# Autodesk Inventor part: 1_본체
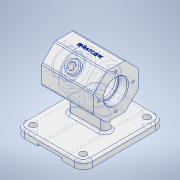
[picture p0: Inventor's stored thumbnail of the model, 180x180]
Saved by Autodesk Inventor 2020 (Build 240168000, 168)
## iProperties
Created: 2022-10
Part Number: 1_본체
Material: 알루미늄 6061
Document SubType Name: Modeling
Designer: USER
Density: 2.7 g/cm^3
Appearance: 알루미늄 - 평지
Mass: 559.154 g
Surface Area: 567.652 cm^2
Volume: 207.094 cm^3
Author: USER
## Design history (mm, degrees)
sketch "스케치1"
  geometry: L1 (46, 55)-(-46, 55); L2 (-46, 55)-(-46, -55); L3 (-46, -55)-(46, -55); L4 (46, -55)-(46, 55); L5 (46, 55)-(-46, -55); L6 (-46, 55)-(46, -55); 1 further point
  constraints: 12 end point, 2 midpoint, 2 parallel, 1 horizontal, 1 perpendicular
  dimensions: "d0" = 92 distance of L2.end L3.end; "d1" = 110 distance of L3.end L1.start
extrude "돌출1" new body sketch "스케치1" distance "d2" = 10; taper "d3" = 0 deg
sketch "스케치2"
  geometry: L1 (30, 3)-(62, 3); L2 (62, 3)-(62, 0); L3 (62, 0)-(30, 0); L4 (30, 0)-(30, 3); L5 (0, 0)-(92, 0) reference; 2 further points
  constraints: 8 end point, 2 midpoint, 2 parallel, 1 horizontal, 1 perpendicular
  dimensions: "d4" = 32 distance of L2.end L3.end; "d5" = 3 distance of L1.end L2.end
extrude "돌출2" cut sketch "스케치2" extent not by distance; stored distance "d6" = 0; taper "d7" = 0 deg
fillet "모깎기1" dims "d8" = 12
sketch "스케치3"
  geometry: L1 (74.426, 30)-(92, 12.426); L2 (92, 12.426)-(92, -12.426); L3 (92, -12.426)-(74.426, -30); L4 (74.426, -30)-(49.574, -30); L5 (49.574, -30)-(32, -12.426); L6 (32, -12.426)-(32, 12.426); L7 (32, 12.426)-(49.574, 30); L8 (49.574, 30)-(74.426, 30); L9 (0, -55)-(0, -43) reference; L10 (0, 0)-(62, 0); C1 r 30 at (62, 0); 1 further point
  constraints: 18 end point, 2 coincident, 2 horizontal, 1 centre point, 1 tangent, 17 other
  dimensions: "d9" = 62 distance from line of L9 point (62, 0); "d10" = 60 diameter of C1
extrude "돌출3" join sketch "스케치3" stored distance "d11" = 70; taper "d12" = 0 deg
sketch "스케치4"
  geometry: L1 (-20, 0)-(20, 0); L2 (-20, -6)-(20, -6); L3 (20, 6)-(-20, 6); A1 r 6 centre (-20, 0) between (-20, 6) and (-20, -6); A2 r 6 centre (20, 0) between (20, -6) and (20, 6); 2 further points
  constraints: 8 end point, 4 point on circle, 4 tangent, 2 centre point, 1 coincident, 1 horizontal, 1 midpoint, 1 parallel
  dimensions: "d13" = 40 distance of L1.start L1.end; "d14" = 12 distance between parallel lines of L3 L2
extrude "돌출4" join sketch "스케치4" stored distance "d15" = 70; taper "d16" = 0 deg
sketch "스케치5"
  geometry: L1 (74.426, 30)-(92, 12.426) reference; L2 (83.213, 21.213)-(88.87, 15.556); L3 (88.87, 15.556)-(92.406, 19.092); L4 (92.406, 19.092)-(86.749, 24.749); L5 (86.749, 24.749)-(83.213, 21.213); 1 further point
  constraints: 8 end point, 2 parallel, 1 midpoint, 1 perpendicular, 1 point on line
  dimensions: "d17" = 16 diameter of L3 L5; "d18" = 5 distance between parallel lines of L1 L4
revolve "회전1" sketch "스케치5" stored, may be unused: angle "d19" = 90 deg
sketch "스케치6"
  geometry: L1 (-35, 74.426)-(-35, 49.574) reference; L2 (-35, 92)-(35, 92) reference; L3 (-35, 62)-(0, 62); L4 (0, 92)-(0, 62); L5 (-20, 62)-(20, 62); L6 (20, 62)-(20, 84); L7 (17, 87)-(-17, 87); L8 (-20, 84)-(-20, 62); A1 r 3 centre (-17, 84) between (-17, 87) and (-20, 84); A2 r 3 centre (17, 84) between (20, 84) and (17, 87); 3 further points
  constraints: 12 end point, 4 point on circle, 4 point on line, 4 tangent, 3 midpoint, 2 centre point, 2 horizontal, 2 parallel, 1 equal radius, 1 perpendicular, 1 vertical
  dimensions: "d20" = 50 diameter of L7 L5; "d21" = 40 distance of point (20, 87) point (-20, 87); "d22" = 3 radius of A1
revolve "회전2" sketch "스케치6" stored, may be unused: angle "d23" = 90 deg
sketch "스케치7"
  geometry: L1 (-35, 74.426)-(-35, 49.574) reference; L2 (-35, 62)-(-20, 62); L3 (-20, 84)-(-20, 40) reference; L4 (-35, 62)-(-35, 78); L5 (-35, 78)-(-23, 78); L6 (-23, 78)-(-23, 76); L7 (-23, 76)-(-20, 76); L8 (-20, 76)-(-20, 62); 1 further point
  constraints: 12 end point, 3 perpendicular, 2 midpoint, 2 vertical, 1 point on line
  dimensions: "d24" = 32 diameter of L5 L2; "d25" = 28 diameter of L7 L2; "d26" = 12 distance between parallel lines of L4 L6
revolve "회전3" sketch "스케치7" stored, may be unused: angle "d27" = 90 deg
chamfer "모따기1" distance "d28" = 1; stored, may be unused: second distance "d29" = 2, angle "d30" = 45 deg
fillet "모깎기2" dims "d31" = 0.3
sketch "스케치8" dims "d32" = 46
  geometry: L1 (0, 62)-(0, 85); C1 r 17 at (0, 62) reference; 2 further points
  constraints: 2 coincident, 2 end point, 1 vertical, 1 vertical alignment, 2 other
hole "구멍1" sketch "스케치8" at (0, 85) diameter "d33" = 3.242; stored, may be unused: countersink angle "d37" = 90 deg, drill point angle "d39" = 118 deg; dims "d34" = 8, "d35" = 4, "d36" = 2, "d38" = 10
sketch "스케치9"
  geometry: C1 r 8 at (0, 0) reference; C2 r 4 at (0, 0); 1 further point
  constraints: 1 centre point, 1 coincident
  dimensions: "d43" = 8 diameter of C2
extrude "돌출5" cut sketch "스케치9" stored distance "d44" = 70; taper "d45" = 0 deg
sketch "스케치10"
  geometry: L1 (20, -6)-(-20, -6) reference; L2 (-20, 6)-(20, 6) reference; L3 (34, 55)-(-34, 55) reference; L4 (-46, 43)-(-46, -43) reference; L5 (-34, -55)-(34, -55) reference; L6 (46, -43)-(46, 43) reference; A1 r 6 centre (-20, 0) between (-20, 6) and (-20, -6) reference; A2 r 6 centre (20, 0) between (20, -6) and (20, 6) reference; A3 r 12 centre (-34, 43) between (-34, 55) and (-46, 43) reference; A4 r 12 centre (-34, -43) between (-46, -43) and (-34, -55) reference; A5 r 12 centre (34, -43) between (34, -55) and (46, -43) reference; A6 r 12 centre (34, 43) between (46, 43) and (34, 55) reference; 5 further points
  constraints: 4 coincident
hole "구멍2" sketch "스케치10" at (-34, 43), (34, 43), (34, -43), (-34, -43) diameter "d46" = 9; stored, may be unused: countersink angle "d50" = 90 deg, drill point angle "d52" = 118 deg; dims "d47" = 8, "d48" = 4, "d49" = 2, "d51" = 10
sketch "스케치11"
  geometry: L1 (18.408, 14.828)-(51.592, 14.828); L2 (51.592, 14.828)-(51.592, 10.025); L3 (51.592, 10.025)-(18.408, 10.025); L4 (18.408, 10.025)-(18.408, 14.828); 2 further points
  constraints: 1 coincident, 1 horizontal, 2 other
  dimensions: "d53" = 33.18318 distance of L1.start L1.end; "d54" = 4.80326 distance of L1.end L2.end; "d55" = 16.59159 distance from line of L2 point (35, 12.426) (= 0.5 x d53); "d56" = 2.40163 distance from line of point (35, 12.426) L3 (= 0.5 x d54)
feature "엠보싱1" sketch "스케치11" dims "d0" = 92, "d1" = 110, "d57" = 0.5, "d58" = 0
fillet "모깎기3" dims "d59" = 3
fillet "모깎기4" dims "d60" = 1
node "솔리드1"
mirror "미러1"
pattern_circular "원형 패턴1" dims angle "d41" = 360 deg
mirror "미러2"
node "투영된 루프1"
feature "A9D066F2-1C7D-4E18-AEED-F7BC21143FA4" dims "d46" = 9, "d47" = 8, "d48" = 4, "d49" = 2, "d50" = 90 deg, "d51" = 10, "d52" = 118 deg
